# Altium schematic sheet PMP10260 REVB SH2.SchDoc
size 431 x 279 mm; Date: Not shown in title block; ApprovedBy: Not shown in title block; CheckedBy: Not shown in title block; Author: Not shown in title block; CompanyName: Not shown in title block; Engineer: Not shown in title block; Organization: Not shown in title block; Address1: Not shown in title block; Address2: Not shown in title block; Address3: Not shown in title block; Address4: Not shown in title block; DocumentNumber: 2; Revision: Use project parameter SCH_Rev; SheetNumber: 2; SheetTotal: 3; PageSetup: Record=PageOptions¦CenterHorizontal=True¦CenterVertical=True¦PrintScale=1.00¦XCorrection=1.00¦YCorrection=1.00¦PrintKind=0¦BorderSize=5000000¦LeftOffset=0¦BottomOffset=0¦Orientation=2¦PaperLength=1000¦PaperWidth=1000¦Scale=100¦PaperSource=15¦PrintQuality=600¦MediaType=1¦DitherType=10¦PaperKind=Letter¦PrintScaleMode=1
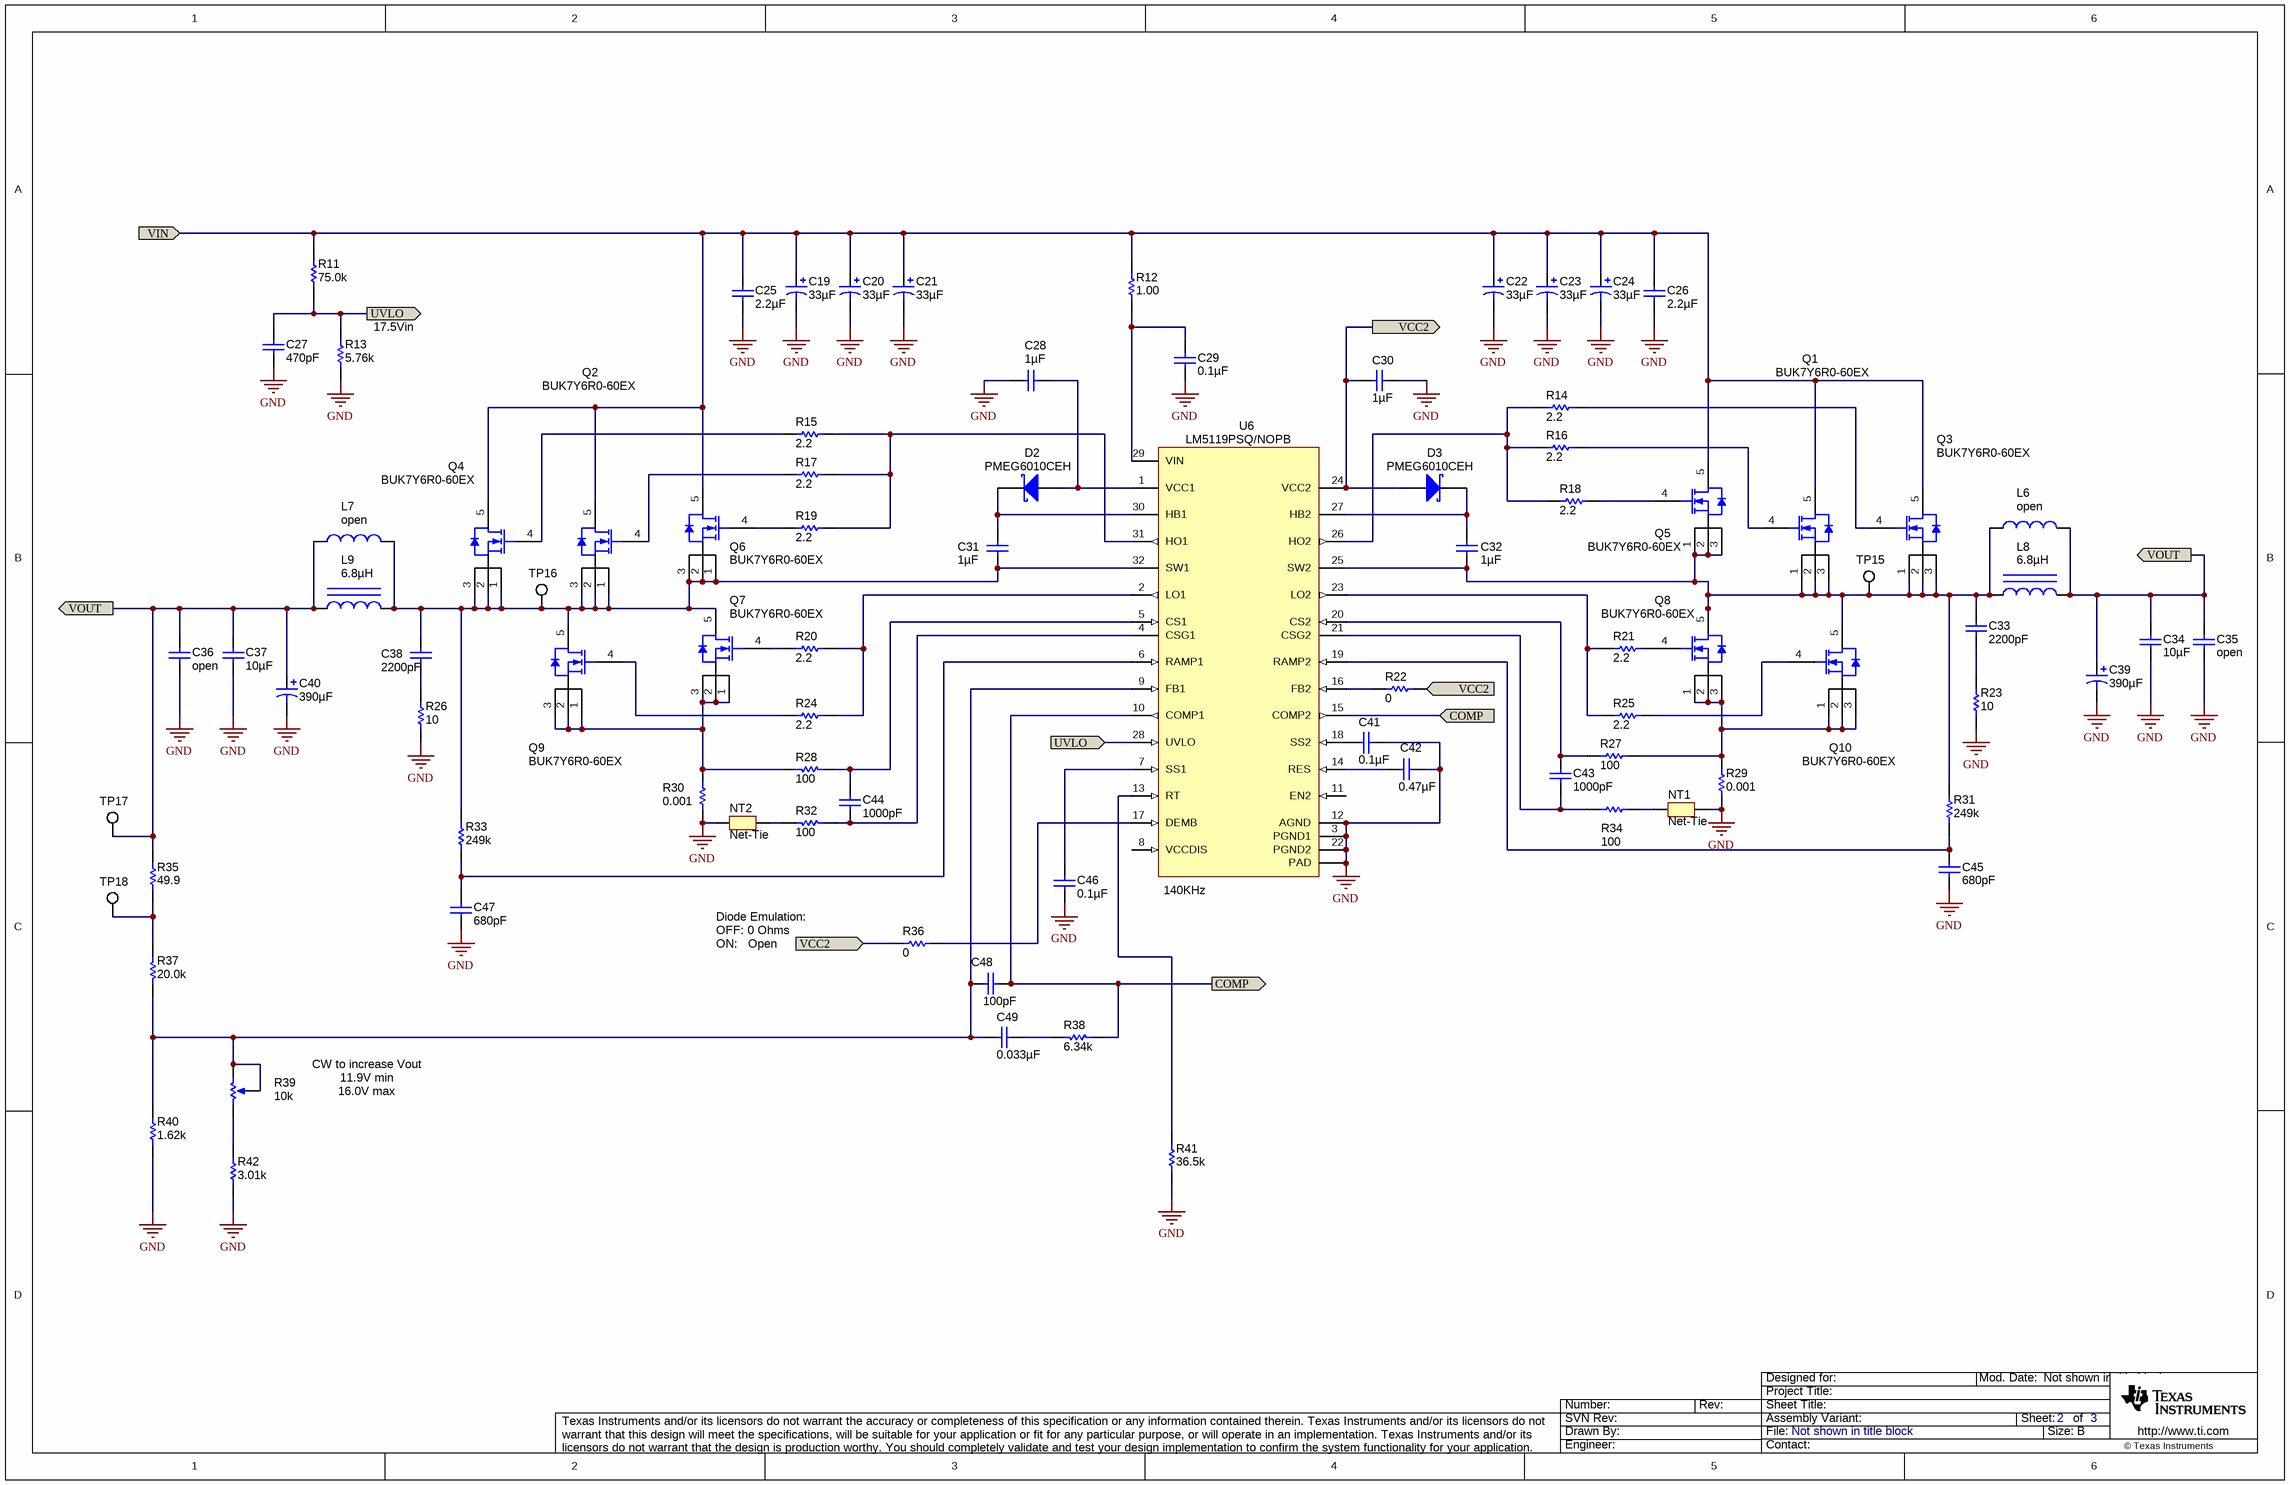
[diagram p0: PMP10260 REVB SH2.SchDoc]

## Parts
C19  ValueDisplayed: 33µF  [SXV_E12]  (hidden comment: 63SXV33M)
C20  ValueDisplayed: 33µF  [SXV_E12]  (hidden comment: 63SXV33M)
C21  ValueDisplayed: 33µF  [SXV_E12]  (hidden comment: 63SXV33M)
C22  ValueDisplayed: 33µF  [SXV_E12]  (hidden comment: 63SXV33M)
C23  ValueDisplayed: 33µF  [SXV_E12]  (hidden comment: 63SXV33M)
C24  ValueDisplayed: 33µF  [SXV_E12]  (hidden comment: 63SXV33M)
C25  ValueDisplayed: 2.2µF  [1210]  (hidden comment: GRM32ER72A225KA35L)
C26  ValueDisplayed: 2.2µF  [1210]  (hidden comment: GRM32ER72A225KA35L)
C27  ValueDisplayed: 470pF  [0603]  (hidden comment: C1608C0G1H471J)
C28  ValueDisplayed: 1µF  [0603]  (hidden comment: C1608X7R1E105K080AB)
C29  ValueDisplayed: 0.1µF  [0805_HV]  (hidden comment: C2012X7R2A104K)
C30  ValueDisplayed: 1µF  [0603]  (hidden comment: C1608X7R1E105K080AB)
C31  ValueDisplayed: 1µF  [0603]  (hidden comment: C1608X7R1E105K080AB)
C32  ValueDisplayed: 1µF  [0603]  (hidden comment: C1608X7R1E105K080AB)
C33  ValueDisplayed: 2200pF  [0603]  (hidden comment: C0603C222K5RAC)
C34  ValueDisplayed: 10µF  [1210]  (hidden comment: GMK325AB7106MM-T)
C35  ValueDisplayed: open  [1210]
C36  ValueDisplayed: open  [1210]
C37  ValueDisplayed: 10µF  [1210]  (hidden comment: GMK325AB7106MM-T)
C38  ValueDisplayed: 2200pF  [0603]  (hidden comment: C0603C222K5RAC)
C39  ValueDisplayed: 390µF  [SM_RADIAL_8MM]  (hidden comment: 20SVPF390M)
C40  ValueDisplayed: 390µF  [SM_RADIAL_8MM]  (hidden comment: 20SVPF390M)
C41  ValueDisplayed: 0.1µF  [0603]  (hidden comment: C1608X7R1H104K)
C42  ValueDisplayed: 0.47µF  [0603]  (hidden comment: C0603C474K4RACTU)
C43  ValueDisplayed: 1000pF  [0603]  (hidden comment: C1608C0G1H102J)
C44  ValueDisplayed: 1000pF  [0603]  (hidden comment: C1608C0G1H102J)
C45  ValueDisplayed: 680pF  [0603]  (hidden comment: C1608C0G1H681J)
C46  ValueDisplayed: 0.1µF  [0603]  (hidden comment: C1608X7R1H104K)
C47  ValueDisplayed: 680pF  [0603]  (hidden comment: C1608C0G1H681J)
C48  ValueDisplayed: 100pF  [0603]  (hidden comment: C1608C0G1H101J)
C49  ValueDisplayed: 0.033µF  [0603]  (hidden comment: GRM188R71H333KA61D)
D2  PMEG6010CEH  [SOD-123F]
D3  PMEG6010CEH  [SOD-123F]
L6  ValueDisplayed: open  [SER29XX]
L7  ValueDisplayed: open  [SER29XX]
L8  ValueDisplayed: 6.8µH  [SER2915]  (hidden comment: SER2915H-682KL)
L9  ValueDisplayed: 6.8µH  [SER2915]  (hidden comment: SER2915H-682KL)
NT1  Net-Tie  [Net-Tie_10mil]  (net tie, no BOM)
NT2  Net-Tie  [Net-Tie_10mil]  (net tie, no BOM)
Q1  BUK7Y6R0-60EX  [LFPAK56]
Q2  BUK7Y6R0-60EX  [LFPAK56]
Q3  BUK7Y6R0-60EX  [LFPAK56]
Q4  BUK7Y6R0-60EX  [LFPAK56]
Q5  BUK7Y6R0-60EX  [LFPAK56]
Q6  BUK7Y6R0-60EX  [LFPAK56]
Q7  BUK7Y6R0-60EX  [LFPAK56]
Q8  BUK7Y6R0-60EX  [LFPAK56]
Q9  BUK7Y6R0-60EX  [LFPAK56]
Q10  BUK7Y6R0-60EX  [LFPAK56]
R11  value 75.0k  [0603]  (hidden comment: CRCW060375K0FKEA)
R12  value 1.00  [0805]  (hidden comment: CRCW08051R00FKEA)
R13  value 5.76k  [0603]  (hidden comment: CRCW06035K76FKEA)
R14  value 2.2  [0603]  (hidden comment: CRCW06032R20JNEA)
R15  value 2.2  [0603]  (hidden comment: CRCW06032R20JNEA)
R16  value 2.2  [0603]  (hidden comment: CRCW06032R20JNEA)
R17  value 2.2  [0603]  (hidden comment: CRCW06032R20JNEA)
R18  value 2.2  [0603]  (hidden comment: CRCW06032R20JNEA)
R19  value 2.2  [0603]  (hidden comment: CRCW06032R20JNEA)
R20  value 2.2  [0603]  (hidden comment: CRCW06032R20JNEA)
R21  value 2.2  [0603]  (hidden comment: CRCW06032R20JNEA)
R22  value 0  [0603]  (hidden comment: CRCW06030000Z0EA)
R23  value 10  [1206]  (hidden comment: CRCW120610R0JNEA)
R24  value 2.2  [0603]  (hidden comment: CRCW06032R20JNEA)
R25  value 2.2  [0603]  (hidden comment: CRCW06032R20JNEA)
R26  value 10  [1206]  (hidden comment: CRCW120610R0JNEA)
R27  value 100  [0603]  (hidden comment: RC0603FR-07100RL)
R28  value 100  [0603]  (hidden comment: RC0603FR-07100RL)
R29  value 0.001  [2512]  (hidden comment: ERJ-M1WTF1M0U)
R30  value 0.001  [2512]  (hidden comment: ERJ-M1WTF1M0U)
R31  value 249k  [0603]  (hidden comment: CRCW0603249KFKEA)
R32  value 100  [0603]  (hidden comment: RC0603FR-07100RL)
R33  value 249k  [0603]  (hidden comment: CRCW0603249KFKEA)
R34  value 100  [0603]  (hidden comment: RC0603FR-07100RL)
R35  value 49.9  [0603]  (hidden comment: CRCW060349R9FKEA)
R36  value 0  [0603]  (hidden comment: CRCW06030000Z0EA)
R37  value 20.0k  [0603]  (hidden comment: CRCW060320K0FKEA)
R38  ValueDisplayed: 6.34k  [0603]  (hidden comment: CRCW06036K34FKEA)
R39  value 10k  [TRIM_3224W]  (hidden comment: 3224W-2-103E)
R40  value 1.62k  [0603]  (hidden comment: CRCW06031K62FKEA)
R41  value 36.5k  [0603]  (hidden comment: CRCW060336K5FKEA)
R42  value 3.01k  [0603]  (hidden comment: CRCW06033K01FKEA)
TP15  5015  [Testpoint_Keystone_Miniature]  (value not drawn)
TP16  5015  [Testpoint_Keystone_Miniature]  (value not drawn)
TP17  5015  [Testpoint_Keystone_Miniature]  (value not drawn)
TP18  5015  [Testpoint_Keystone_Miniature]  (value not drawn)
U6  LM5119PSQ/NOPB  [RTV0032A]

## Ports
COMP, UVLO, VCC2, VIN, VOUT

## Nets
GND: C19.2(-) C20.2(-) C21.2(-) C22.2(-) C23.2(-) C24.2(-) C25.2 C26.2 C27.2 C28.2 C29.2 C30.2 C34.2 C35.2 C36.2 C37.2 C39.2(-) C40.2(-) C41.1 C42.1 C45.2 C46.2 C47.2 NT1.2 NT2.1 R13.1 R23.1 R26.1 R29.1 R30.1 R40.1 R41.1 R42.1 U6.3(PGND1) U6.12(AGND) U6.22(PGND2) U6.33(PAD)
COMP: C48.1 R38.1 U6.10(COMP1) U6.15(COMP2) ; port COMP
UVLO: C27.1 R11.1 R13.2 U6.28(UVLO) ; port UVLO
VCC2: C30.1 D3.2(A) R22.2 R36.1 U6.24(VCC2) ; port VCC2
VIN: C19.1(+) C20.1(+) C21.1(+) C22.1(+) C23.1(+) C24.1(+) C25.1 C26.1 Q1.5(D) Q2.5(D) Q3.5(D) Q4.5(D) Q5.5(D) Q6.5(D) R11.2 R12.1 ; port VIN
VOUT: C34.1 C35.1 C36.1 C37.1 C39.1(+) C40.1(+) L6.2 L7.1 L8.1 L9.2 R35.2 TP17.1 ; port VOUT
NetC28_1: C28.1 D2.2(A) U6.1(VCC1)
NetC29_1: C29.1 R12.2 U6.29(VIN)
NetC31_1: C31.1 D2.1(K) U6.30(HB1)
NetC31_2: C31.2 C38.1 L7.2 L9.1 Q2.1(S) Q2.2(S) Q2.3(S) Q4.1(S) Q4.2(S) Q4.3(S) Q6.1(S) Q6.2(S) Q6.3(S) Q7.5(D) Q9.5(D) R33.2 TP16.1 U6.32(SW1)
NetC32_1: C32.1 D3.1(K) U6.27(HB2)
NetC32_2: C32.2 C33.1 L6.1 L8.2 Q1.1(S) Q1.2(S) Q1.3(S) Q3.1(S) Q3.2(S) Q3.3(S) Q5.1(S) Q5.2(S) Q5.3(S) Q8.5(D) Q10.5(D) R31.2 TP15.1 U6.25(SW2)
NetC33_2: C33.2 R23.2
NetC38_2: C38.2 R26.2
NetC41_2: C41.2 U6.18(SS2)
NetC42_2: C42.2 U6.14(RES)
NetC43_1: C43.1 R27.1 U6.20(CS2)
NetC43_2: C43.2 R34.1 U6.21(CSG2)
NetC44_1: C44.1 R28.1 U6.5(CS1)
NetC44_2: C44.2 R32.1 U6.4(CSG1)
NetC45_1: C45.1 R31.1 U6.19(RAMP2)
NetC46_1: C46.1 U6.7(SS1)
NetC47_1: C47.1 R33.1 U6.6(RAMP1)
NetC48_2: C48.2 C49.2 R37.1 R39.1(CCW) R39.2(WIPER) R40.2 U6.9(FB1)
NetC49_1: C49.1 R38.2
NetNT1_1: NT1.1 R34.2
NetNT2_2: NT2.2 R32.2
NetQ1_4: Q1.4(G) R16.2
NetQ2_4: Q2.4(G) R17.1
NetQ3_4: Q3.4(G) R14.2
NetQ4_4: Q4.4(G) R15.1
NetQ5_4: Q5.4(G) R18.2
NetQ6_4: Q6.4(G) R19.1
NetQ7_1: Q7.1(S) Q7.2(S) Q7.3(S) Q9.1(S) Q9.2(S) Q9.3(S) R28.2 R30.2
NetQ7_4: Q7.4(G) R20.1
NetQ8_1: Q8.1(S) Q8.2(S) Q8.3(S) Q10.1(S) Q10.2(S) Q10.3(S) R27.2 R29.2
NetQ8_4: Q8.4(G) R21.2
NetQ9_4: Q9.4(G) R24.1
NetQ10_4: Q10.4(G) R25.2
NetR14_1: R14.1 R16.1 R18.1 U6.26(HO2)
NetR15_2: R15.2 R17.2 R19.2 U6.31(HO1)
NetR20_2: R20.2 R24.2 U6.2(LO1)
NetR21_1: R21.1 R25.1 U6.23(LO2)
NetR22_1: R22.1 U6.16(FB2)
NetR35_1: R35.1 R37.2 TP18.1
NetR36_2: R36.2 U6.17(DEMB)
NetR39_3: R39.3(CW) R42.2
NetR41_2: R41.2 U6.13(RT)

Not connected (* = marked no-connect by the designer): L6 3; L7 3; U6 8(VCCDIS) 11(EN2)

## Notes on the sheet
- (near R13) 17.5Vin
- (near U6) 140KHz
- Diode Emulation:
- ON:   Open
- OFF: 0 Ohms
- 11.9V min
- 16.0V max
- CW to increase Vout

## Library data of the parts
C19-C24 = 63SXV33M: CAP, OS-CON, 33uF, 63V, +/-20%, 0.025 ohm, 8.0x11.9mm SMD; Manufacturer: Panasonic; Polarized: Y; CompType: Capacitor; U/M: EA; Cap_F: 0.000033; Tolerance_%: 20; VDC_V: 63; ESR_Ohm: 0.025; IRMS_A: 2.95; TaMin_C: -55; TaMax_C: 105
C25 C26 = GRM32ER72A225KA35L: CAP, CERM, 2.2uF, 100V, +/-10%, X7R, 1210; Manufacturer: MuRata; Polarized: N; CompType: Capacitor; U/M: EA; Cap_F: 0.0000022; Tolerance_%: 10; ESR_Ohm: 0.007; Value1: 0.007 ohm; VDC_V: 100; IRMS_A: 4.4; TaMin_C: -55; TaMax_C: 125
C27 = C1608C0G1H471J: CAP, CERM, 470pF, 50V, +/-5%, C0G/NP0, 0603; Manufacturer: TDK; Polarized: N; CompType: Capacitor; U/M: EA; Cap_F: 0.00000000047; Tolerance_%: 5; ESR_Ohm: 0.0922; Value1: 0.0922 ohm; VDC_V: 50; TaMin_C: -55; TaMax_C: 125
C28 C30-C32 = C1608X7R1E105K080AB: CAP, CERM, 1uF, 25V, +/-10%, X7R, 0603; Manufacturer: TDK; Polarized: N; CompType: Capacitor; U/M: EA; Cap_F: 0.000001; Tolerance_%: 10; Value1: Unknown; VDC_V: 25; TaMin_C: -55; TaMax_C: 125
C29 = C2012X7R2A104K: CAP, CERM, 0.1uF, 100V, +/-10%, X7R, 0805; Manufacturer: TDK; Polarized: N; CompType: Capacitor; U/M: EA; Cap_F: 0.0000001; Tolerance_%: 10; ESR_Ohm: 0.0158; Value1: 0.0158 ohm; VDC_V: 100; TaMin_C: -55; TaMax_C: 125; Cap_Case: 0805
C33 C38 = C0603C222K5RAC: CAP, CERM, 2200pF, 50V, +/-10%, X7R, 0603; Manufacturer: Kemet; Polarized: N; CompType: Capacitor; U/M: EA; Cap_F: 0.0000000022; Tolerance_%: 10; Value1: Unknown; VDC_V: 50; TaMin_C: -55; TaMax_C: 125
C34 C37 = GMK325AB7106MM-T: CAP, CERM, 10uF, 35V, +/-20%, X7R, 1206; Manufacturer: Taiyo Yuden; Polarized: N; CompType: Capacitor; U/M: EA; Cap_F: 0.00001; Tolerance_%: 20; Value1: Unknown; VDC_V: 35; TaMin_C: -55; TaMax_C: 125
C35 C36 = C3225X7R1H335M: CAP, CERM, open, 1210; Manufacturer: TDK; Polarized: N; CompType: Capacitor; Value: 10uF; U/M: EA; Cap_F: 0.0000033; Tolerance_%: 20; Value1: Unknown; VDC_V: 50; Value2: 50V; TempCo: X5R; TaMin_C: -55; TaMax_C: 125
C39 C40 = 20SVP100M: CAP, OS-CON, 390uF, 20V, +/-20%, 0.014 ohm, 8x10 SMD; Manufacturer: Sanyo; Polarized: Y; CompType: Capacitor; U/M: EA; Cap_F: 0.0001; Tolerance_%: 20; ESR_Ohm: 0.024; IRMS_A: 3.32; TaMin_C: -55; TaMax_C: 105; Cap_Case: 8.3x8.3x11.9
C41 C46 = C1608X7R1H104K: CAP, CERM, 0.1uF, 50V, +/-10%, X7R, 0603; Manufacturer: TDK; Polarized: N; CompType: Capacitor; U/M: EA; Cap_F: 0.0000001; Tolerance_%: 10; ESR_Ohm: 0.017; Value1: 0.017 ohm; VDC_V: 50; TaMin_C: -55; TaMax_C: 125
C42 = C0603C474K4RACTU: CAP, CERM, 0.47uF, 16V, +/-10%, X7R, 0603; Manufacturer: Kemet; Polarized: N; CompType: Capacitor; U/M: EA; Cap_F: 0.00000047; Tolerance_%: 10; Value1: Unknown; VDC_V: 16; TaMin_C: -55; TaMax_C: 125
C43 C44 = C1608C0G1H102J: CAP, CERM, 1000pF, 50V, +/-5%, C0G/NP0, 0603; Manufacturer: TDK; Polarized: N; CompType: Capacitor; U/M: EA; Cap_F: 0.000000001; Tolerance_%: 5; ESR_Ohm: 0.0563; Value1: 0.0563 ohm; VDC_V: 50; TaMin_C: -55; TaMax_C: 125
C45 C47 = C1608C0G1H681J: CAP, CERM, 680 pF, 50 V, +/- 5%, C0G/NP0, 0603; Manufacturer: TDK; Polarized: N; CompType: Capacitor; Value: 680pF; U/M: EA; Cap_F: 0.00000000068; Tolerance_%: 5; ESR_ohm: 0.0723; Value1: 0.0723 ohm; VDC_V: 50; Value2: 50V; TaMin_C: -55; TaMax_C: 125
C48 = C1608C0G1H101J: CAP, CERM, 100pF, 50V, +/-5%, C0G/NP0, 0603; Manufacturer: TDK; Polarized: N; CompType: Capacitor; U/M: EA; Cap_F: 0.0000000001; Tolerance_%: 5; ESR_Ohm: 0.1679; Value1: 0.1679 ohm; VDC_V: 50; TaMin_C: -55; TaMax_C: 125
C49 = GRM188R71H333KA61D: CAP, CERM, 0.033uF, 50V, +/-10%, X7R, 0603; Manufacturer: MuRata; Polarized: N; CompType: Capacitor; U/M: EA; Cap_F: 0.000000033; Tolerance_%: 10; Value1: Unknown; VDC_V: 50; TaMin_C: -55; TaMax_C: 125
D2 D3 = PMEG6010CEH,115: Diode, Schottky, 60V, 1A, SOD-123F; Manufacturer: NXP Semiconductor; U/M: EA; Vf_V: 0.57; Value2: 0.57V; Io_A: 1; Vr_V: 60; TJmax_C: 150
L6 L7 = SER29XX: Inductor, open, TH; SymbolCreator: a0411947; Ind_H: 6.8E-6; Imax_A: 40
L8 L9 = SER2915H-682KL: Inductor, Shielded E Core, Ferrite, 6.8uH, 30A, 0.00186 ohm, SMD; Manufacturer: Coilcraft; Ind_H: 6.8E-6; Imax_A: 30; Irms: 30A @ 40C rise; Isat: 36.2A @ 30% inductance drop; U/M: EA
NT1 NT2 = Net-Tie: Single point connection between nets.; SymbolCreator: codlsc
Q1-Q10 = BUK7Y6R0-60EX: MOSFET, N-CH, 60V, 100A, SOT669; Manufacturer: NXP Semiconductor; Alternate Manufacturer: None; SymbolCreator: a0412235; U/M: EA; ChType: N; VdsMax_V: 60; Value1: ? ohm; Value2: 45.4 nC; QgTyp_nC: 45.4; Vgs_V: 20; IdsMax_A: 100
R11 = CRCW060375K0FKEA: RES, 75.0k ohm, 1%, 0.1W, 0603; Manufacturer: Vishay-Dale; CompType: Resistor; Res_ohm: 75000; Value_Code: 75k0; Tolerance_%: 1; Power_W: 0.1; VDC_V: 75; TempCo: 100 ppm/C; EIA_Code: E96; U/M: EA
R12 = CRCW08051R00FKEA: RES, 1.00 ohm, 1%, 0.125W, 0805; Manufacturer: Vishay-Dale; CompType: Resistor; Res_ohm: 1; Value_Code: 1R00; Power_W: 0.125; VDC_V: 150; TempCo: 100 ppm/C; EIA_Code: E96; U/M: EA
R13 = CRCW06035K76FKEA: RES, 5.76k ohm, 1%, 0.1W, 0603; Manufacturer: Vishay-Dale; CompType: Resistor; Res_ohm: 5760; Value_Code: 5k76; Tolerance_%: 1; Power_W: 0.1; VDC_V: 75; TempCo: 100 ppm/C; EIA_Code: E96; U/M: EA
R14-R21 R24 R25 = CRCW06032R20JNEA: RES, 2.2 ohm, 5%, 0.1W, 0603; Manufacturer: Vishay-Dale; CompType: Resistor; Value_Code: 2R20; Tolerance_%: 5; Power_W: 0.1; VDC_V: 75; TempCo: 200 ppm/C; EIA_Code: E24; U/M: EA
R22 R36 = CRCW06030000Z0EA: RES, 0 ohm, 5%, 0.1W, 0603; Manufacturer: Vishay-Dale; CompType: Resistor; Value_Code: 0000; Tolerance_%: 5; Power_W: 0.1; VDC_V: 75; TempCo: 200 ppm/C; EIA_Code: E24; U/M: EA
R23 R26 = CRCW120610R0JNEA: RES, 10 ohm, 5%, 0.25W, 1206; Manufacturer: Vishay-Dale; CompType: Resistor; Value_Code: 10R0; Tolerance_%: 5; Power_W: 0.25; VDC_V: 200; TempCo: 200 ppm/C; EIA_Code: E24; U/M: EA
R27 R28 R32 R34 = RC0603FR-07100RL: RES, 100 ohm, 1%, 0.1W, 0603; Manufacturer: Yageo America; CompType: Resistor; Value_Code: 100R; Tolerance_%: 1; Power_W: 0.1; VDC_V: 150; TempCo: 200 ppm/C; EIA_Code: E96; U/M: EA
R29 R30 = CSRN2512FKR200: RES, 0.001ohm, 1%, 2W, 2512; Manufacturer: Panasonic; CompType: Resistor; Tolerance_%: 1; Power_W: 2; TempCo: 200 ppm/C; EIA_Code: E96; U/M: EA
R31 R33 = CRCW0603249KFKEA: RES, 249k ohm, 1%, 0.1W, 0603; Manufacturer: Vishay-Dale; CompType: Resistor; Res_ohm: 249000; Tolerance_%: 1; Power_W: 0.1; VDC_V: 75; TempCo: 100 ppm/C; EIA_Code: E96; U/M: EA
R35 = CRCW060349R9FKEA: RES, 49.9 ohm, 1%, 0.1W, 0603; Manufacturer: Vishay-Dale; CompType: Resistor; Value_Code: 49R9; Tolerance_%: 1; Power_W: 0.1; VDC_V: 75; TempCo: 100 ppm/C; EIA_Code: E96; U/M: EA
R37 = CRCW060320K0FKEA: RES, 20.0k ohm, 1%, 0.1W, 0603; Manufacturer: Vishay-Dale; CompType: Resistor; Res_ohm: 20000; Value_Code: 20k0; Tolerance_%: 1; Power_W: 0.1; VDC_V: 75; TempCo: 100 ppm/C; EIA_Code: E96; U/M: EA
R38 = CRCW06036K34FKEA: RES, 6.34 k, 1%, 0.1 W, 0603; Manufacturer: Vishay-Dale; CompType: Resistor; Value: 6.34k; Res_ohm: 6340; Value_Code: 6k34; Tolerance_%: 1; Power_W: 0.1; Value2: 0.1W; VDC_V: 75; TempCo: 100 ppm/C; EIA_Code: E96; U/M: EA
R39 = 3224W-2-103E: TRIMMER, 10K, 0.25W, SMD; Manufacturer: Bourns; Sim Note: Enter the Resistance value and the set point into parameter fields.; SymbolCreator: a0412235
R40 = CRCW06031K62FKEA: RES, 1.62k ohm, 1%, 0.1W, 0603; Manufacturer: Vishay-Dale; CompType: Resistor; Res_ohm: 1620; Value_Code: 1k62; Tolerance_%: 1; Power_W: 0.1; VDC_V: 75; TempCo: 100 ppm/C; EIA_Code: E96; U/M: EA
R41 = CRCW060336K5FKEA: RES, 36.5k ohm, 1%, 0.1W, 0603; Manufacturer: Vishay-Dale; CompType: Resistor; Res_ohm: 36500; Value_Code: 36k5; Tolerance_%: 1; Power_W: 0.1; VDC_V: 75; TempCo: 100 ppm/C; EIA_Code: E96; U/M: EA
R42 = CRCW06033K01FKEA: RES, 3.01k ohm, 1%, 0.1W, 0603; Manufacturer: Vishay-Dale; CompType: Resistor; Res_ohm: 3010; Value_Code: 3k01; Tolerance_%: 1; Power_W: 0.1; VDC_V: 75; TempCo: 100 ppm/C; EIA_Code: E96; U/M: EA
TP15-TP18 = 5015: Test Point, Miniature, SMT; Manufacturer: Keystone; CompType: Test Point Loop; U/M: EA
U6 = LM5119PSQ/NOPB: LM5119/LM5119Q Wide Input Range Dual Synchronous Buck Controller, RTV0032A; Alternate Manufacturer: None; Manufacturer: Texas Instruments; SymbolCreator: a0411947; CompType: IC; U/M: EA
